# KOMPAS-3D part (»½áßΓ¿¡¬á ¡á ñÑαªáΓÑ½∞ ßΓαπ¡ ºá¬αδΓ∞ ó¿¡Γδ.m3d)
File: created 10.11.2015 18:49:21, last saved 10.11.2015 18:53:26.
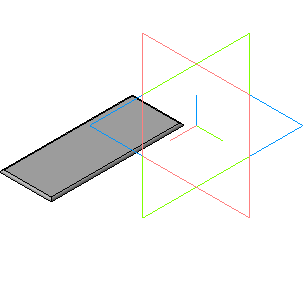
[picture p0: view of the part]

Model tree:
1. Эскиз:1
2. Операция выдавливания:1
     Расстояние 1 = 1
3. Скругление:1
     Радиус = 1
